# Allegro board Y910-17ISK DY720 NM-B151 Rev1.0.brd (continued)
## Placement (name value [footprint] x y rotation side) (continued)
C659  -  [C_0603NEW]  219.81 130.45 90 bottom
C660  -  [C_0603NEW]  217.46 151.46 0 top
C661  -  [C_0603NEW]  221.65 151.21 180 bottom
C662  -  [C_0402NEW]  222.68 130.76 180 top
C663  -  [C_0402NEW]  226.11 130.51 180 top
C664  -  [C_0402NEW]  226.11 131.4 180 top
C665  -  [C_0603NEW]  217.46 152.73 0 top
C666  VAL  [C_0402-NV]  241.52 131.02 180 top
C667  VAL  [C_0402-NV]  244.22 135.41 0 top
C668  VAL  [C_0402-NV]  244.09 131.04 0 top
C669  VAL  [C_0402-NV]  241.9 133.18 180 top
C670  -  [C_0402NEW]  226.11 132.92 180 top
C671  -  [C_0402NEW]  226.11 133.81 180 top
C672  -  [C_0402NEW]  222.68 134.7 180 top
C673  -  [C_0402NEW]  222.68 135.59 180 top
C674  -  [C_0402NEW]  226.11 135.33 180 top
C675  -  [C_0402NEW]  226.11 136.22 180 top
C676  -  [C_0603NEW]  223.17 128.98 0 bottom
C677  -  [C_0603NEW]  228.38 128.98 180 bottom
C678  -  [C_0603NEW]  216.82 132.41 0 bottom
C679  -  [C_0402NEW]  222.68 137.11 180 top
C680  -  [C_0402NEW]  222.68 138 180 top
C681  -  [C_0402NEW]  226.11 137.75 180 top
C682  -  [C_0402NEW]  226.11 138.64 180 top
C683  -  [C_0603NEW]  212.88 127.08 180 bottom
C684  -  [C_0603NEW]  221.39 125.81 180 top
C685  VAL  [C_0402-NV]  244.04 132.52 270 top
C686  VAL  [C_0402-NV]  249.27 140.8 0 top
C687  -  [C_0603NEW]  223.81 126.95 180 top
C688  VAL  [C_0402-NV]  263.37 132.06 180 top
C689  VAL  [C_0402-NV]  254.78 140.41 270 top
C690  VAL  [C_0402-NV]  259.81 121.62 90 top
C691  VAL  [C_0402-NV]  263.49 123.4 180 top
C692  VAL  [C_0402-NV]  263.24 139.22 180 top
C693  -  [C_0603NEW]  224 123.71 270 top
C694  -  [C_0603NEW]  234.03 124.86 270 top
C695  -  [C_0402NEW]  242.29 120.6 270 top
C696  -  [C_0402NEW]  241.22 120.6 180 top
C697  VAL  [C_0402-NV]  244.19 129.24 0 top
C698  VAL  [C_0402-NV]  260.85 140.41 270 top
C699  -  [C_0402NEW]  44.55 38.1 90 bottom
C701  VAL  [C_0402-NV]  242.16 124.77 0 top
C702  VAL  [C_0402-NV]  241.07 123.14 90 top
C703  VAL  [C_0402-NV]  242.67 122.63 180 top
C704  -  [C_0603NEW]  217.39 127.02 270 bottom
C705  -  [C_0603NEW]  218.66 127.02 270 bottom
C868  -  [C_0402NEW]  222.68 140.41 180 top
C869  -  [C_0402NEW]  222.68 139.53 180 top
C870  -  [C_0402NEW]  226.11 140.16 180 top
C871  -  [C_0402NEW]  183.46 145.29 90 top
C872  -  [C_0402NEW]  184.83 144.22 0 top
C873  -  [C_0402NEW]  184.84 142.19 0 top
C874  -  [C_0402NEW]  226.11 141.05 180 top
C875  -  [C_0402NEW]  222.68 142.7 180 top
C876  -  [C_0402NEW]  222.68 141.81 180 top
C877  -  [C_0402NEW]  226.11 142.57 180 top
C878  -  [C_0402NEW]  226.11 143.46 180 top
C879  -  [C_0402NEW]  222.68 145.24 180 top
C880  -  [C_0402NEW]  222.68 144.35 180 top
C881  -  [C_0402NEW]  226.11 145.11 180 top
C882  -  [C_0402NEW]  226.11 146 180 top
C883  -  [C_0402NEW]  222.68 146.89 180 top
C884  -  [C_0402NEW]  222.68 147.78 180 top
C885  -  [C_0402NEW]  226.11 147.53 180 top
C886  -  [C_0402NEW]  226.11 148.42 180 top
C887  -  [C_0402NEW]  248.98 170.01 0 top
C888  -  [C_0402NEW]  210.66 198.63 90 bottom
C889  -  [C_0402NEW]  245.97 171.2 90 bottom
C890  -  [C_0402NEW]  249.02 171.1 270 bottom
C907  -  [C_0402NEW]  246.97 170.01 180 top
C908  -  [C_0402NEW]  293.01 159.92 0 top
C909  -  [C_0402NEW]  281.15 171.1 270 bottom
C910  -  [C_0402NEW]  294.05 158.83 180 bottom
C915  -  [C_0603NEW]  172.21 138.36 90 top
C916  -  [C_0603NEW]  160.37 133.68 90 top
C917  -  [C_0603NEW]  163.01 133.68 90 top
C918  -  [C_0603NEW]  179.8 133.11 270 top
C919  -  [C_0402NEW]  177.01 134.24 90 top
C920  -  [C_0402NEW]  164.56 133.25 270 top
C921  -  [C_0402NEW]  172.05 133.51 270 top
C922  -  [C_0402NEW]  186.28 134.06 90 top
C923  -  [C_0402NEW]  186.28 133.18 0 top
C924  -  [C_0402NEW]  163.46 138.33 0 top
C925  -  [C_0402NEW]  169.01 138.92 0 top
C926  -  [C_0402NEW]  170.66 133.51 270 top
C927  -  [C_0402NEW]  179.55 134.19 90 top
C928  -  [C_0402NEW]  184.68 136.99 0 top
C929  -  [C_0805NEW]  199.91 169.5 0 top
C930  -  [C_0402NEW]  191.87 157.38 270 top
C931  -  [C_0402NEW]  182.39 155.17 180 top
C932  -  [C_0402NEW]  188.41 156.37 0 top
C933  -  [C_0402NEW]  188.41 157.25 0 top
C934  -  [C_0402NEW]  182.82 152.54 0 top
C935  -  [C_0402NEW]  182.37 151.58 0 top
C936  -  [C_0402NEW]  182.79 149.2 270 top
C937  -  [C_0402NEW]  183.67 149.21 270 top
C938  -  [C_0201NEW]  184.25 157.51 270 top
C939  -  [C_0201NEW]  183.52 155.03 90 top
C940  -  [C_0201NEW]  184.08 155.02 90 top
C941  -  [C_B2]  205.71 169.75 180 bottom
C942  -  [C_B2]  202.87 169.75 0 bottom
C944  -  [C_0201NEW]  184.67 150.83 0 top
C945  -  [C_0201NEW]  186.32 152.73 180 top
C946  -  [C_0201NEW]  185.14 149.65 90 top
C947  -  [C_0201NEW]  184.63 151.95 0 top
C948  -  [C_0201NEW]  184.63 151.39 0 top
C949  -  [C_0402NEW]  177.03 138.33 90 top
C950  -  [C_0201NEW]  154.27 139.06 270 top
C951  -  [C_0201NEW]  186.38 138.57 270 top
C952  -  [C_B2]  173.22 171.4 180 bottom
C953  -  [C_B2]  194.94 168.74 180 top
C954  -  [C_B2]  195.06 169.75 180 bottom
C955  -  [C_0603NEW]  160.43 173.43 0 top
C956  -  [C_0603NEW]  160.43 174.7 0 top
C957  -  [C_0603NEW]  160.94 169.37 0 bottom
C958  -  [C_0603NEW]  160.89 170.69 0 bottom
C959  -  [C_0603NEW]  160.81 172.04 0 bottom
C960  -  [C_0603NEW]  154.21 174.83 180 top
C961  -  [C_0603NEW]  154.21 173.56 180 top
C962  -  [C_0603NEW]  165.51 172.55 180 bottom
C974  -  [C_0402NEW]  172.07 150.09 270 top
C975  -  [C_0402NEW]  177.4 149.18 90 top
C976  -  [C_0402NEW]  176.51 149.18 90 top
C977  -  [C_0402NEW]  175.62 150.09 270 top
C978  -  [C_0402NEW]  174.73 150.09 270 top
C979  -  [C_0402NEW]  176.37 146.76 180 top
C980  -  [C_0402NEW]  179.71 152.57 270 top
C981  -  [C_0402NEW]  178.28 152.61 270 top
C982  -  [C_0402NEW]  176.4 152.57 270 top
C983  -  [C_0402NEW]  172.57 143.78 0 top
C984  -  [C_0402NEW]  173.61 152.55 270 top
C985  -  [C_0402NEW]  172.09 151.63 90 top
C986  -  [C_0402NEW]  182.27 143.11 0 top
C987  -  [C_0402NEW]  173.15 147.81 180 top
C988  -  [C_0402NEW]  180.14 149.18 90 top
C1007  -  [C_0402NEW]  172.95 149.18 90 top
C1008  -  [C_0402NEW]  173.84 149.18 90 top
C1009  -  [C_0402NEW]  179.23 150.09 270 top
C1010  -  [C_0402NEW]  182.26 140.35 0 top
C1011  -  [C_0402NEW]  182.26 144 0 top
C1012  -  [C_0402NEW]  181.17 139.59 180 top
C1013  -  [C_0402NEW]  181.84 138.29 180 top
C1014  -  [C_0402NEW]  175.49 143.78 180 top
C1015  -  [C_0402NEW]  176.43 143.78 0 top
C1016  -  [C_0402NEW]  179.17 143.78 180 top
C1017  -  [C_0402NEW]  180.29 143.81 0 top
C1018  -  [C_0402NEW]  182.21 141.68 0 top
C1019  -  [C_0402NEW]  177.97 138.28 0 top
C1020  -  [C_0402NEW]  174.63 138.32 180 top
C1021  -  [C_0402NEW]  178.34 150.09 270 top
C1040  -  [C_0201NEW]  179.35 156.62 270 top
C1041  -  [C_0201NEW]  178.8 156.62 270 top
C1042  -  [C_0201NEW]  175.42 154.02 270 top
C1043  -  [C_0201NEW]  174.86 154.02 270 top
C1044  -  [C_0201NEW]  173.12 139.53 0 top
C1045  -  [C_0201NEW]  180.37 156.62 270 top
C1046  -  [C_0201NEW]  180.93 156.62 270 top
C1047  -  [C_0201NEW]  176.43 156.62 270 top
C1048  -  [C_0201NEW]  176.99 156.62 270 top
C1049  -  [C_0201NEW]  174.63 156.62 270 top
C1050  -  [C_0201NEW]  174.07 156.62 270 top
C1051  -  [C_0201NEW]  175.42 152.06 270 top
C1052  -  [C_0201NEW]  174.86 152.06 270 top
C1053  -  [C_0201NEW]  179.35 154 270 top
C1054  -  [C_0201NEW]  175.86 148.03 0 top
C1055  -  [C_0201NEW]  175.86 147.48 0 top
C1056  -  [C_0201NEW]  172.57 146.51 0 top
C1057  -  [C_0201NEW]  176.08 139.47 180 top
C1058  -  [C_0201NEW]  174.76 146.89 180 top
C1059  -  [C_0201NEW]  178.32 146.89 180 top
C1060  -  [C_0201NEW]  181.16 146.26 0 top
C1061  -  [C_0201NEW]  179.38 146.89 0 top
C1062  -  [C_0201NEW]  177.39 151.46 90 top
C1086  -  [C_0201NEW]  179.42 148.03 0 top
C1087  -  [C_0201NEW]  179.42 147.48 0 top
C1088  -  [C_0201NEW]  178.28 148.03 180 top
C1089  -  [C_0201NEW]  178.28 147.48 180 top
C1090  -  [C_0201NEW]  178.99 140.03 180 top
C1091  -  [C_0201NEW]  178.99 139.47 180 top
C1092  -  [C_0201NEW]  174.29 140.03 0 top
C1093  -  [C_0201NEW]  174.29 139.47 0 top
C1094  -  [C_0201NEW]  180.21 141.18 0 top
C1095  -  [C_0201NEW]  180.21 140.62 0 top
C1096  -  [C_0201NEW]  179.04 141.43 180 top
C1097  -  [C_0201NEW]  179.04 140.87 180 top
C1098  -  [C_0201NEW]  176.5 141.43 0 top
C1099  -  [C_0201NEW]  176.5 140.87 0 top
C1100  -  [C_0201NEW]  180.94 148.03 0 top
C1101  -  [C_0201NEW]  180.94 147.48 0 top
C1102  -  [C_0201NEW]  175.43 141.43 180 top
C1103  -  [C_0201NEW]  175.43 140.87 180 top
C1104  -  [C_0201NEW]  181.45 149.61 270 top
C1105  -  [C_0201NEW]  182.01 149.61 270 top
C1106  -  [C_0201NEW]  173.06 154.02 270 top
C1107  -  [C_0201NEW]  172.5 154.02 270 top
C1108  -  [C_0201NEW]  181.16 154.02 270 top
C1132  -  [C_0201NEW]  172.44 141.43 0 top
C1133  -  [C_0201NEW]  172.44 140.87 0 top
C1134  -  [C_0201NEW]  174.72 148.03 180 top
C1135  -  [C_0201NEW]  174.72 147.48 180 top
C1136  -  [C_0201NEW]  180.82 142.57 0 top
C1137  -  [C_0201NEW]  180.82 142.01 0 top
C1138  -  [C_0201NEW]  180 142.57 180 top
C1139  -  [C_0201NEW]  180 142.01 180 top
C1140  -  [C_0201NEW]  178.25 142.57 0 top
C1141  -  [C_0201NEW]  178.25 142.01 0 top
C1142  -  [C_0201NEW]  177.21 142.57 180 top
C1143  -  [C_0201NEW]  177.21 142.01 180 top
C1144  -  [C_0201NEW]  174.59 142.65 0 top
C1145  -  [C_0201NEW]  174.59 142.09 0 top
C1146  -  [C_0201NEW]  177.78 154.02 270 top
C1147  -  [C_0201NEW]  173.54 142.66 180 top
C1148  -  [C_0201NEW]  180.56 152.05 270 top
C1149  -  [C_0201NEW]  181.72 154 270 top
C1150  -  [C_0201NEW]  173.54 142.1 180 top
C1151  -  [C_0201NEW]  172.82 152.04 270 top
C1152  -  [C_0201NEW]  178.8 154.02 270 top
C1153  -  [C_0201NEW]  181.2 152.06 270 top
C1154  -  [C_0201NEW]  177.22 154.02 270 top
C1178  -  [C_B2]  155.95 169.75 0 bottom
C1179  -  [C_B2]  156.03 169.37 0 top
C1180  -  [C_B2]  185.67 171.66 180 bottom
C1181  -  [C_0805NEW]  187.64 174.7 180 bottom
C1182  -  [C_0805NEW]  175.14 174.2 0 bottom
C1183  -  [C_0805NEW]  187.38 168.99 180 bottom
C1184  -  [C_0805NEW]  163.08 174.07 0 bottom
C1326  -  [C_0402NEW]  282.4 170.38 180 top
C1327  -  [C_0805NEW]  178.66 194.35 270 bottom
C1329  -  [C_0402NEW]  300.58 58.3 90 top
C1330  -  [C_0402NEW]  303.68 58.25 0 top
C1332  -  [C_0402NEW]  300.53 61.29 180 top
C1333  -  [C_0402NEW]  303.7 69.42 180 top
C1335  -  [C_B2]  16.76 65.23 180 top
C1338  -  [C_0402NEW]  295.07 72.98 180 top
C1339  -  [C_0402NEW]  303.58 73.23 180 top
C1340  -  [C_0402NEW]  205.61 130.64 180 bottom
C1341  -  [C_0402NEW]  210.79 154.71 90 top
C1342  -  [C_0402NEW]  292.91 173.31 180 top
C1343  VAL  [C_0402-NV]  242.29 126.83 0 top
C1353  -  [C_0402NEW]  293.14 124.84 0 top
C1354  -  [C_0402NEW]  294.22 126.8 180 bottom
C1355  -  [C_0402NEW]  294.18 123.78 180 bottom
C1359  -  [C_0402NEW]  64.66 9.22 0 top
C1361  -  [C_0402NEW]  64.66 8.33 0 top
C1362  -  [C_0402NEW]  75.15 15.9 270 top
C1363  -  [C_0402NEW]  77.69 6.61 90 top
C1364  -  [C_0402NEW]  65.76 3.81 90 top
C1365  -  [C_0402NEW]  66.64 3.81 90 top
C1367  -  [C_0402NEW]  66.34 7.32 180 top
C1368  -  [C_0402NEW]  75.03 5.36 270 top
C1369  -  [C_0402NEW]  76.8 4.45 90 top
C1370  -  [C_0402NEW]  57.37 12.22 270 bottom
C1371  -  [C_B2]  62.71 16.99 270 bottom
C1372  -  [C_0402NEW]  65.37 17.66 90 bottom
C1373  -  [C_0402NEW]  257.86 92.61 270 top
C1374  -  [C_0402NEW]  259.94 91.57 90 bottom
C1375  -  [C_0402NEW]  257.91 91.52 90 bottom
C1376  -  [C_0402NEW]  91 17.73 0 top
C1377  -  [C_0402NEW]  89.25 18.57 270 top
C1378  -  [C_0402NEW]  90.14 18.57 270 top
C1379  -  [C_0603NEW]  88.11 17.42 90 top
C1385  -  [C_0402NEW]  288.94 22 0 top
C1386  -  [C_0603NEW]  288.7 20.91 0 top
C1391  -  [C_0402NEW]  307.61 105.49 0 top
C1392  -  [C_0603NEW]  307.37 104.4 0 top
C1393  -  [C_0603NEW]  219.93 127.02 270 bottom
C1394  VAL  [C_0402-NV]  230.35 124.54 90 bottom
C1395  VAL  [C_0402-NV]  226.03 127.84 0 bottom
C1396  VAL  [C_0402-NV]  218.41 126.7 270 top
C1397  VAL  [C_0402-NV]  244.19 124.67 0 top
C1398  VAL  [C_0402-NV]  221.08 126.32 270 bottom
C1399  -  [C_0402NEW]  222.6 114.33 270 bottom
C1400  -  [C_0402NEW]  222.6 115.19 90 bottom
C1401  -  [C_0402NEW]  281.78 86.87 90 bottom
C1402  -  [C_0402NEW]  280.77 86.87 90 bottom
C1405  VAL  [C_0402-NV]  244.19 127.51 0 top
C1406  VAL  [C_0402-NV]  244.19 128.35 0 top
C1407  VAL  [C_0402-NV]  225.9 123.9 180 bottom
C2027  -  [C_0201NEW]  58.57 75.76 270 bottom
C2028  -  [C_0201NEW]  56.94 77.64 90 bottom
C2029  -  [C_0201NEW]  59.2 75.76 270 bottom
C2030  -  [C_0201NEW]  57.58 77.64 90 bottom
C2031  -  [C_0201NEW]  54.55 78.25 270 bottom
C2032  -  [C_0201NEW]  55.72 73.57 90 bottom
C2033  -  [C_0201NEW]  55.19 78.25 270 bottom
C2034  -  [C_0201NEW]  56.36 73.57 90 bottom
C2035  -  [C_0201NEW]  52.17 76.44 270 bottom
C2036  -  [C_0201NEW]  48.06 74.37 0 bottom
C2037  -  [C_0201NEW]  52.8 76.44 270 bottom
C2038  -  [C_0201NEW]  48.06 73.74 0 bottom
C2039  -  [C_0201NEW]  49.4 77.36 270 bottom
C2040  -  [C_0201NEW]  47.47 77.77 90 bottom
C2041  -  [C_0201NEW]  50.03 77.36 270 bottom
C2042  -  [C_0201NEW]  48.1 77.77 90 bottom
C2043  -  [C_0201NEW]  69.78 74.37 0 bottom
C2044  -  [C_0201NEW]  69.78 73.82 0 bottom
C2045  -  [C_0201NEW]  69.78 72.85 0 bottom
C2046  -  [C_0402NEW]  44.37 78.57 180 bottom
C2047  -  [C_0201NEW]  69.78 72.29 0 bottom
C2048  -  [C_0402NEW]  45.23 78.57 0 bottom
C2049  -  [C_0201NEW]  69.78 71.33 0 bottom
C2050  -  [C_0201NEW]  69.78 70.77 0 bottom
C2051  -  [C_0201NEW]  69.78 69.85 0 bottom
C2052  -  [C_0201NEW]  69.78 69.29 0 bottom
C2055  -  [C_0201NEW]  53.82 99.05 270 top
C2056  -  [C_0201NEW]  59.82 63.58 0 bottom
C2057  -  [C_0201NEW]  59.82 63.02 0 bottom
C2058  -  [C_0201NEW]  59.82 62.34 0 bottom
C2059  -  [C_0201NEW]  59.82 61.78 0 bottom
C2060  -  [C_0201NEW]  59.82 61.14 0 bottom
C2061  -  [C_0201NEW]  59.82 60.58 0 bottom
C2062  -  [C_0201NEW]  59.82 59.85 0 bottom
C2063  -  [C_0201NEW]  59.82 59.26 0 bottom
C2066  -  [C_0201NEW]  44.1 83.98 180 bottom
C2067  -  [C_0201NEW]  44.1 83.42 180 bottom
C2068  -  [C_0201NEW]  44.1 82.25 180 bottom
C2069  -  [C_0201NEW]  44.1 82.81 180 bottom
C2070  -  [C_0201NEW]  30.12 68.82 90 bottom
C2071  -  [C_0201NEW]  29.56 68.82 90 bottom
C2072  -  [C_0201NEW]  52.01 83.23 270 top
C2073  -  [C_0201NEW]  52.41 83.85 0 top
C2074  -  [C_0201NEW]  49.44 86.52 180 top
C2076  -  [C_0201NEW]  51.09 88.42 0 top
C2077  -  [C_0201NEW]  52.52 85.79 270 top
C2078  -  [C_0201NEW]  53.18 85.71 315 top
C2079  -  [C_0201NEW]  53.08 88.24 45 top
C2080  -  [C_0201NEW]  53.35 87.58 0 top
C2081  -  [C_0201NEW]  52.52 88.87 90 top
C2082  -  [C_0201NEW]  47.78 88.95 180 top
C2083  -  [C_0201NEW]  42.39 90.82 90 top
C2084  -  [C_0201NEW]  48.14 87.84 180 top
C2085  -  [C_0402NEW]  42.26 90.68 90 bottom
C2086  -  [C_0402NEW]  41.37 90.68 90 bottom
C2087  -  [C_0402NEW]  43.15 90.68 90 bottom
C2088  -  [C_0402NEW]  44.04 90.68 90 bottom
C2089  -  [C_0201NEW]  51.09 87.84 0 top
C2090  -  [C_0201NEW]  50.05 86.9 315 top
C2091  -  [C_0201NEW]  48.79 88.16 135 top
C2092  -  [C_0201NEW]  47.54 86.15 90 top
C2093  -  [C_0201NEW]  46.92 85.88 180 top
C2094  -  [C_0201NEW]  46.22 85.28 270 top
C2095  -  [C_0201NEW]  47.41 84.94 315 top
C2096  -  [C_0201NEW]  49.97 80.09 0 top
C2097  -  [C_0201NEW]  50.57 84.93 90 top
C2098  -  [C_0201NEW]  49.97 80.72 0 top
C2099  -  [C_0201NEW]  49.97 81.36 0 top
C2100  -  [C_0402NEW]  54.58 98.83 270 top
C2101  -  [C_0201NEW]  52.34 87.25 180 top
C2102  -  [C_0201NEW]  51.46 86.62 225 top
C2103  -  [C_0603NEW]  42.01 94.38 270 bottom
C2104  -  [C_0603NEW]  43.28 94.38 270 bottom
C2105  -  [C_0603NEW]  40.74 94.38 270 bottom
C2107  -  [C_0201NEW]  49.4 83.81 270 top
C2108  -  [C_0201NEW]  49.44 84.61 180 top
C2109  -  [C_0402NEW]  45.94 83.47 270 top
C2110  -  [C_0402NEW]  46.12 87.51 270 top
C2111  -  [C_0201NEW]  48.25 87.14 270 top
C2112  -  [C_0201NEW]  48.66 83.25 90 top
C2113  -  [C_0603NEW]  38.32 79.01 270 bottom
C2114  -  [C_0603NEW]  35.78 80.03 90 top
C2115  -  [C_0603NEW]  37.05 80.03 90 top
C2116  -  [C_0603NEW]  36.8 80.03 90 bottom
C2117  -  [C_0201NEW]  32.1 69.08 270 bottom
C2118  -  [C_0201NEW]  36.96 72.34 180 top
C2119  -  [C_0603NEW]  38.32 75.33 270 bottom
C2120  -  [C_B2]  40.63 77.04 180 top
C2121  -  [C_0201NEW]  28.54 69.21 270 bottom
C2122  -  [C_0402NEW]  13.74 80.52 90 bottom
C2123  -  [C_0402NEW]  13.56 77.63 270 bottom
C2124  -  [C_0402NEW]  36.29 70.13 270 bottom
C2125  -  [C_0402NEW]  14.62 80.52 90 bottom
C2126  -  [C_0402NEW]  14.45 76.71 90 bottom
C2127  -  [C_0201NEW]  33.48 71.02 0 top
C2128  -  [C_0201NEW]  31.72 73.45 90 top
C2129  -  [C_0201NEW]  30.41 77.3 0 top
C2130  -  [C_0201NEW]  30.41 76.66 0 top
C2131  -  [C_0201NEW]  32.74 74.84 90 top
C2133  -  [C_0402NEW]  60.24 86.06 180 top
C2134  -  [C_0402NEW]  60.24 85.17 180 top
C2136  -  [C_0603NEW]  30.17 80.59 90 bottom
C2139  -  [C_0402NEW]  29.43 79.76 90 top
C2151  -  [C_0201NEW]  51.89 85.16 270 top
C2153  -  [C_0402NEW]  58.85 87.07 180 top
C2154  -  [C_0402NEW]  58.85 87.96 180 top
C2163  -  [C_0201NEW]  84.77 84.79 0 bottom
C2164  -  [C_0201NEW]  84.77 83.26 0 bottom
C2165  -  [C_0201NEW]  84.77 87.84 0 bottom
C2166  -  [C_0402NEW]  82.82 86.08 0 top
C2167  -  [C_0402NEW]  82.8 82.99 0 top
C2168  -  [C_0402NEW]  82.82 87.46 0 top
C2169  -  [C_0402NEW]  79.78 82.76 0 top
C2170  -  [C_0402NEW]  80.94 88.85 180 top
C2171  -  [C_0402NEW]  85.64 78.06 180 top
C2172  -  [C_0603NEW]  84.74 79.2 0 top
C2174  -  [C_0805NEW]  220.06 107.94 90 bottom
C2175  -  [C_B2]  222.6 108.23 270 bottom
C2176  -  [C_0603NEW]  282.5 128.73 0 top
C2177  -  [C_0603NEW]  274.43 157.47 90 top
C2178  -  [C_0603NEW]  273.16 157.47 90 top
C2179  -  [C_0603NEW]  282.5 123.78 0 top
C2180  -  [C_0603NEW]  257.02 157.37 90 top
C2181  -  [C_0603NEW]  255.75 157.37 90 top
C2182  -  [C_0603NEW]  238.16 158.96 180 top
C2183  -  [C_0603NEW]  282.35 133.94 0 top
C2184  -  [C_0603NEW]  282.35 132.67 0 top
C2185  -  [C_0603NEW]  282.73 116.41 0 top
C2186  -  [C_0603NEW]  282.73 117.68 0 top
C2187  -  [C_0603NEW]  263.11 107.59 270 top
C2188  -  [C_0603NEW]  261.08 107.59 270 top
C2189  VAL  [C_0402-NV]  245.33 118.7 270 top
C2193  VAL  [C_0402-NV]  246.25 121.49 90 top
C2198  VAL  [C_0402-NV]  248.53 121.49 90 top
C2204  VAL  [C_0402-NV]  223.62 122.25 0 bottom
C2207  VAL  [C_0402-NV]  245.41 121.49 90 top
C2208  VAL  [C_0402-NV]  250.21 121.49 90 top
C2209  VAL  [C_0402-NV]  249.52 119.33 270 top
C2210  VAL  [C_0402-NV]  243.71 119.84 0 top
C2211  VAL  [C_0402-NV]  244.27 121.19 0 top
C2212  VAL  [C_0402-NV]  244.27 122.03 0 top
C2213  VAL  [C_0402-NV]  244.06 118.57 0 top
C2214  VAL  [C_0402-NV]  247.11 117.81 180 top
C2215  VAL  [C_0402-NV]  247.42 121.11 180 top
C2216  VAL  [C_0402-NV]  247.49 119.21 270 top
C2217  VAL  [C_0402-NV]  233.78 112.35 270 bottom
C2218  VAL  [C_0402-NV]  247.11 116.92 180 top
C2219  VAL  [C_0402-NV]  249.37 121.49 90 top
C2220  VAL  [C_0402-NV]  232.89 112.35 270 bottom
C2221  -  [C_0402NEW]  286.56 174.2 180 top
C2222  -  [C_0402NEW]  300.78 77.68 180 top
C2319  VAL  [C_0402-NV]  252.19 121.11 0 top
C2320  -  [C_0603NEW]  250.92 104.28 270 top
C2321  VAL  [C_0402-NV]  262.1 140.16 0 top
C2322  -  [C_0603NEW]  248.64 104.28 270 top
C2323  -  [C_0603NEW]  242.29 141.24 270 top
C2324  VAL  [C_0402-NV]  260.06 133.81 0 top
C2325  VAL  [C_0402-NV]  261.58 133.81 0 top
C2326  VAL  [C_0402-NV]  247.37 125.43 180 top
C2327  -  [C_0603NEW_S]  250.89 135.22 270 top
C2328  VAL  [C_0402-NV]  252.02 125.43 0 top
C2329  VAL  [C_0402-NV]  253.33 121.49 90 top
C2330  VAL  [C_0402-NV]  250.47 125.43 0 top
C2331  VAL  [C_0402-NV]  248.92 125.43 0 top
C2332  VAL  [C_0402-NV]  257.78 140.92 0 top
C2333  -  [C_0603NEW]  241.27 147.08 90 top
C2334  VAL  [C_0402-NV]  245.82 125.43 180 top
C2335  -  [C_0603NEW_S]  248.79 135.22 270 top
C2336  VAL  [C_0402-NV]  263.49 127.21 270 top
C2337  VAL  [C_0402-NV]  260.45 124.03 0 top
C2338  VAL  [C_0402-NV]  257.41 124.03 0 top
C2339  VAL  [C_0402-NV]  252.27 140.41 270 top
C2340  VAL  [C_0402-NV]  253.97 124.03 180 top
C2341  VAL  [C_0402-NV]  252.45 138 180 top
C2342  -  [C_0603NEW]  239.17 143.21 180 top
C2343  VAL  [C_0402-NV]  249.27 140.03 0 top
C2344  VAL  [C_0402-NV]  257.78 122 0 top
C2345  -  [C_0603NEW_S]  256.59 126.82 270 top
C2346  VAL  [C_0402-NV]  254.6 122 0 top
C2347  VAL  [C_0402-NV]  263.49 125.94 180 top
C2348  VAL  [C_0402-NV]  252.02 128.22 0 top
C2349  VAL  [C_0402-NV]  262.03 124.03 0 top
C2350  VAL  [C_0402-NV]  250.47 128.22 0 top
C2351  VAL  [C_0402-NV]  263.49 122.51 180 top
C2352  -  [C_0603NEW]  239.43 149.69 0 top
C2353  VAL  [C_0402-NV]  248.92 128.22 0 top
C2354  -  [C_0603NEW]  260.83 130.32 90 top
C2355  VAL  [C_0402-NV]  247.37 128.22 180 top
C2356  VAL  [C_0402-NV]  252.19 121.95 0 top
C2357  VAL  [C_0402-NV]  256.26 140.92 0 top
C2358  VAL  [C_0402-NV]  252.02 126.83 0 top
C2359  VAL  [C_0402-NV]  250.47 126.83 0 top
C2360  VAL  [C_0402-NV]  248.92 126.83 0 top
C2361  VAL  [C_0402-NV]  255.76 124.03 180 top
C2362  VAL  [C_0402-NV]  253.11 140.41 270 top
C2363  -  [C_0603NEW_S]  257.99 126.82 270 top
C2364  VAL  [C_0402-NV]  247.37 126.83 180 top
C2365  VAL  [C_0402-NV]  245.82 126.83 180 top
C2366  VAL  [C_0402-NV]  261.97 122 0 top
C2367  VAL  [C_0402-NV]  245.82 128.22 180 top
C2368  VAL  [C_0402-NV]  263.24 138.38 180 top
C2369  VAL  [C_0402-NV]  260.07 138 0 top
C2370  VAL  [C_0402-NV]  256.9 138 180 top
C2371  -  [C_0603NEW]  259.56 131.72 270 top
C2372  VAL  [C_0402-NV]  247.42 122 180 top
C2373  VAL  [C_0402-NV]  261.6 138 0 top
C2374  VAL  [C_0402-NV]  255.48 136.6 180 top
C2375  -  [C_0603NEW]  257.02 130.32 90 top
C2376  VAL  [C_0402-NV]  257.01 136.6 180 top
C2377  VAL  [C_0402-NV]  258.53 136.6 0 top
C2378  VAL  [C_0402-NV]  260.06 136.6 0 top
C2379  VAL  [C_0402-NV]  258.55 138 0 top
C2380  -  [C_0603NEW]  254.48 130.32 90 top
C2381  VAL  [C_0402-NV]  250.74 124.03 0 top
C2382  VAL  [C_0402-NV]  247.45 124.03 0 top
C2383  -  [C_0603NEW]  250.67 131.72 270 top
C2384  VAL  [C_0402-NV]  251.05 140.03 180 top
C2385  VAL  [C_0402-NV]  263.11 135.13 180 top
C2386  VAL  [C_0402-NV_S]  249.02 136.6 0 top
C2387  VAL  [C_0402-NV_S]  250.67 136.6 0 top
C2388  -  [C_0603NEW]  249.4 130.32 90 top
C2389  VAL  [C_0402-NV]  258.93 124.03 0 top
C2390  -  [C_0603NEW]  248.13 131.72 270 top
C2391  VAL  [C_0402-NV]  250.67 138 0 top
C2392  VAL  [C_0402-NV]  263.11 133.94 180 top
C2393  VAL  [C_0402-NV]  257.78 140.08 0 top
C2394  -  [C_0603NEW]  265.41 119.7 315 top
C2395  -  [C_0603NEW]  264.32 137.24 180 top
C2396  -  [C_0603NEW]  264.32 129.11 180 top
C2397  -  [C_0603NEW]  272.12 139.79 135 top
C2398  VAL  [C_0402-NV]  251.05 121.49 90 top
C2399  VAL  [C_0402-NV]  259.18 140.41 270 top
C2400  VAL  [C_0402-NV]  255.8 121.62 90 top
C2401  VAL  [C_0402-NV]  257.78 121.11 0 top
C2402  VAL  [C_0402-NV]  258.92 121.62 90 top
C2403  VAL  [C_0402-NV]  260.7 121.62 90 top
C2404  VAL  [C_0402-NV]  261.97 121.11 0 top
C2405  VAL  [C_0402-NV]  263.49 131.14 180 top
C2406  VAL  [C_0402-NV]  263.49 124.79 180 top
C2407  VAL  [C_0402-NV]  256.64 121.62 90 top
C2408  -  [C_0603NEW]  263.51 140.81 45 top
C2409  -  [C_0603NEW]  264.5 120.24 135 top
C2410  -  [C_0201NEW]  84.77 82.63 0 bottom
C2411  -  [C_0201NEW]  84.77 87.2 0 bottom
C2412  -  [C_0201NEW]  84.77 85.68 0 bottom
C2413  -  [C_0201NEW]  84.77 86.31 0 bottom
C2414  -  [C_0201NEW]  84.77 84.15 0 bottom
C2415  VAL  [C_0402-NV]  254.6 121.11 0 top
C2416  VAL  [C_0402-NV]  241.14 129.87 90 top
C2425  -  [C_0402NEW]  293.14 125.76 0 top
C2439  -  [C_0402NEW]  258.85 92.61 270 top
C2440  -  [C_B2]  216.1 177.88 0 top
C2441  -  [C_B2]  273.17 184.74 180 top
C2442  VAL  [C_0402-NV]  244.19 126.57 0 top
C2443  VAL  [C_0402-NV]  228.7 124.54 90 bottom
C2444  VAL  [C_0402-NV]  223.11 127.84 180 bottom
C2445  VAL  [C_0402-NV]  244.19 125.73 0 top
C2446  VAL  [C_0402-NV]  244.19 123.78 0 top
C2447  VAL  [C_0402-NV]  244.32 122.89 0 top
C2448  -  [C_0603NEW]  230.45 173.34 90 top
C2449  -  [C_0603NEW]  230.45 176.08 90 top
C2450  -  [C_0603NEW]  246.45 176.54 90 top
C2451  -  [C_0603NEW]  246.1 178.58 270 bottom
C2452  -  [C_0603NEW]  238.67 179.78 0 bottom
C2453  -  [C_0603NEW]  231.59 168.56 90 top
C2454  -  [C_0603NEW]  231.72 173.34 90 top
C2455  -  [C_0603NEW]  231.72 176.08 90 top
C2456  -  [C_0603NEW]  245.18 176.54 90 top
C2457  -  [C_0603NEW]  231.11 177.18 90 bottom
C2458  -  [C_0603NEW]  241.08 179.78 0 bottom
C2459  -  [C_0402NEW]  245.08 173.96 90 top
C2460  -  [C_0402NEW]  240 168.17 90 top
C2461  -  [C_0402NEW]  245.23 167.08 270 top
C2462  -  [C_0402NEW]  245.23 165.25 270 top
C2463  -  [C_0402NEW]  230.98 173.36 90 bottom
C2464  -  [C_0402NEW]  230.98 175.14 90 bottom
C2465  -  [C_0402NEW]  240.83 171.59 270 top
C2466  -  [C_0402NEW]  245.97 165.26 270 bottom
C2467  -  [C_0402NEW]  236.96 168.39 90 top
C2468  -  [C_0402NEW]  239.18 173.97 270 top
C2469  -  [C_0402NEW]  237.72 176.37 90 top
C2470  -  [C_0402NEW]  236.07 171.47 90 top
C2471  -  [C_0402NEW]  237 166.79 180 top
C2472  -  [C_0402NEW]  245.93 167.16 270 bottom
C2473  -  [C_0402NEW]  245.97 173.87 90 bottom
C2474  -  [C_0402NEW]  231.94 166.81 270 top
C2475  -  [C_0402NEW]  240 165.88 90 top
C2476  -  [C_0402NEW]  229.97 173.36 90 bottom
C2477  -  [C_0603NEW]  264.45 167.47 180 top
C2478  -  [C_0603NEW]  264.36 168.97 90 top
C2479  -  [C_0603NEW]  248.48 176.41 90 top
C2480  -  [C_0603NEW]  264.13 176.42 90 bottom
C2481  -  [C_0603NEW]  249.14 176.29 90 bottom
C2482  -  [C_0603NEW]  263.26 176.41 90 top
C2483  -  [C_0603NEW]  263.26 164.55 90 top
C2484  -  [C_0603NEW]  249.8 176.43 90 top
C2485  -  [C_0603NEW]  249.8 173.84 90 top
C2486  -  [C_0603NEW]  257.33 179.78 0 bottom
C2487  -  [C_0603NEW]  256.32 179.78 180 bottom
C2488  -  [C_0402NEW]  263.19 175.42 270 top
C2489  -  [C_0402NEW]  263.12 169.21 90 top
C2490  -  [C_0402NEW]  255.82 174.3 270 top
C2491  -  [C_0402NEW]  258.93 171.47 90 top
C2492  -  [C_0402NEW]  258.04 168.34 90 top
C2493  -  [C_0402NEW]  249.02 165.01 270 bottom
C2494  -  [C_0402NEW]  249.02 173.99 90 bottom
C2495  -  [C_0402NEW]  249.98 165.03 270 top
C2496  -  [C_0402NEW]  254.93 168.42 90 top
C2497  -  [C_0402NEW]  254.04 171.53 270 top
C2498  -  [C_0402NEW]  257.28 176.27 90 top
C2499  -  [C_0402NEW]  258.11 165.97 270 top
C2500  -  [C_0402NEW]  249.02 166.81 270 bottom
C2501  -  [C_0402NEW]  263.98 175.42 270 bottom
C2502  -  [C_0402NEW]  248.89 173.13 270 bottom
C2503  -  [C_0402NEW]  264 173.51 270 bottom
C2504  -  [C_0402NEW]  249.98 166.86 270 top
C2505  -  [C_0402NEW]  254.93 165.92 270 top
C2506  -  [C_0402NEW]  266.03 175.39 90 bottom
C2507  -  [C_0402NEW]  266.03 173.49 90 bottom
C2508  -  [C_0402NEW]  281.02 167.41 270 bottom
C2509  -  [C_0402NEW]  281.02 165.38 270 bottom
C2510  -  [C_0402NEW]  275.13 165.83 90 top
C2511  -  [C_0402NEW]  280.2 167.33 270 top
C2512  -  [C_0402NEW]  275.12 169.44 270 top
C2513  -  [C_0402NEW]  272.78 176.33 90 top
C2514  -  [C_0603NEW]  279.02 179 180 top
C2515  -  [C_0603NEW]  279.02 180.4 180 top
C2516  -  [C_0603NEW]  266.82 164.83 90 top
C2517  -  [C_0603NEW]  266.8 176.55 90 top
C2518  -  [C_0603NEW]  281.15 178.96 270 bottom
C2519  -  [C_0603NEW]  280.44 176.98 270 top
C2520  -  [C_0603NEW]  265.09 176.42 90 top
C2521  -  [C_0603NEW]  266.69 173.21 90 top
C2522  -  [C_0603NEW]  272.45 179.78 0 bottom
C2523  -  [C_0603NEW]  265.91 177.82 90 bottom
C2524  -  [C_0603NEW]  270.16 179.78 180 bottom
C2525  -  [C_0402NEW]  280.2 165.4 270 top
C2526  -  [C_0402NEW]  271.89 165.98 270 top
C2527  -  [C_0402NEW]  281.02 173.99 90 bottom
C2528  -  [C_0402NEW]  281.02 173.13 270 bottom
C2529  -  [C_0402NEW]  275.88 171.55 270 top
C2530  -  [C_0402NEW]  274.36 174.04 270 top
C2531  -  [C_0402NEW]  271.12 171.48 90 top
C2532  -  [C_0402NEW]  271.89 168.36 90 top
C2533  -  [C_0402NEW]  280.2 173.88 270 top
C2534  -  [C_0402NEW]  266.8 168.5 270 top
C2535  -  [C_0603NEW]  302.86 146.57 90 bottom
C2536  -  [C_0603NEW]  301.99 146.57 90 top
C2537  -  [C_0603NEW]  300.24 144.62 0 top
C2538  -  [C_0603NEW]  297.62 144.62 0 top
C2539  -  [C_0603NEW]  302.86 150.38 90 bottom
C2540  -  [C_0603NEW]  302.09 156.33 270 top
C2541  -  [C_0603NEW]  301.96 150.47 90 top
C2542  -  [C_0603NEW]  299 158.08 0 top
C2543  -  [C_0603NEW]  300.51 143.72 0 bottom
C2544  -  [C_0603NEW]  302.86 156.35 270 bottom
C2545  -  [C_0603NEW]  288.15 144.36 0 top
C2546  -  [C_0402NEW]  298.47 143.84 0 bottom
C2547  -  [C_0402NEW]  299.2 150.47 0 top
C2548  -  [C_0402NEW]  295.94 158.86 180 bottom
C2549  -  [C_0402NEW]  297.71 158.83 0 bottom
C2550  -  [C_0402NEW]  288.95 149.79 180 top
C2551  -  [C_0402NEW]  288.09 158.04 180 top
C2552  -  [C_0402NEW]  293.16 157.97 0 top
C2553  -  [C_0402NEW]  296.88 157.97 180 top
C2554  -  [C_0402NEW]  287.83 158.83 180 bottom
C2555  -  [C_0402NEW]  296.72 143.84 180 bottom
C2556  -  [C_0402NEW]  297.16 151.95 180 top
C2557  -  [C_0402NEW]  294.45 148.95 0 top
C2558  -  [C_0402NEW]  289.92 158.04 180 top
C2559  -  [C_0402NEW]  288.93 152.96 180 top
C2560  -  [C_0402NEW]  291.17 149.71 0 top
C2561  -  [C_0402NEW]  292.28 152.96 180 top
C2562  -  [C_0402NEW]  291.77 144.45 180 top
C2563  -  [C_0402NEW]  289.73 158.83 180 bottom
C2564  -  [C_0402NEW]  294.53 136.63 0 top
C2565  -  [C_0402NEW]  288.27 126.85 180 bottom
C2566  -  [C_0402NEW]  296.16 126.8 180 bottom
C2567  -  [C_0402NEW]  297.17 126.8 0 bottom
C2568  -  [C_0402NEW]  288.42 127.69 180 top
C2569  -  [C_0402NEW]  297.07 126.7 180 top
C2570  -  [C_0402NEW]  291.62 141.15 180 top
C2571  -  [C_0402NEW]  297.05 127.69 180 top
C2572  -  [C_0603NEW]  300.2 127.58 180 top
C2573  -  [C_0603NEW]  299.53 141.32 0 top
C2574  -  [C_0603NEW]  302.11 131.25 270 top
C2575  -  [C_0603NEW]  296.58 141.32 0 top
C2576  -  [C_0603NEW]  302.86 131.21 270 bottom
C2577  -  [C_0603NEW]  299.5 141.94 0 bottom
C2578  -  [C_0603NEW]  302.86 134.26 90 bottom
C2579  -  [C_0603NEW]  302.22 139.98 90 top
C2580  -  [C_0603NEW]  287.75 141.18 0 top
C2581  -  [C_0603NEW]  302.86 139.84 90 bottom
C2582  -  [C_0603NEW]  302.24 134.28 90 top
C2583  -  [C_0402NEW]  289.12 132.7 180 top
C2584  -  [C_0402NEW]  290.61 132.69 0 top
C2585  -  [C_0402NEW]  297.33 141.81 0 bottom
C2586  -  [C_0402NEW]  297.08 133.66 180 top
C2587  -  [C_0402NEW]  291.43 135.87 0 top
C2588  -  [C_0402NEW]  298.92 134.98 0 top
C2589  -  [C_0402NEW]  289 135.87 180 top
C2590  -  [C_0402NEW]  290.3 126.85 180 bottom
C2591  -  [C_0402NEW]  290.27 127.69 180 top
C2592  -  [C_0402NEW]  296.34 141.81 180 bottom
C2593  -  [C_0603NEW]  300.77 108.54 0 bottom
C2594  -  [C_0603NEW]  302.86 112.92 270 bottom
C2595  -  [C_0603NEW]  302.86 115.46 90 bottom
C2596  -  [C_0603NEW]  302.86 118.76 90 bottom
C2597  -  [C_0603NEW]  297.75 109.57 0 top
C2598  -  [C_0603NEW]  302.11 112.91 270 top
C2599  -  [C_0603NEW]  302.09 115.41 90 top
C2600  -  [C_0603NEW]  302.1 118.76 90 top
C2601  -  [C_0603NEW]  300.37 109.57 0 top
C2602  -  [C_0603NEW]  287.81 109.68 0 top
C2603  -  [C_0603NEW]  299.12 123.03 0 top
C2604  -  [C_0402NEW]  296.31 108.79 0 bottom
C2605  -  [C_0402NEW]  296.08 123.78 180 bottom
C2606  -  [C_0402NEW]  287.95 123.78 180 bottom
C2607  -  [C_0402NEW]  298.09 108.79 0 bottom
C2608  -  [C_0402NEW]  297.71 123.78 0 bottom
C2609  -  [C_0402NEW]  291.38 109.68 180 top
C2610  -  [C_0402NEW]  299.33 115.42 0 top
C2611  -  [C_0402NEW]  289.86 123.78 180 bottom
C2612  -  [C_0402NEW]  297.28 116.89 180 top
C2613  -  [C_0402NEW]  294.58 113.9 0 top
C2614  -  [C_0402NEW]  292.41 117.91 180 top
C2615  -  [C_0402NEW]  291.3 114.66 0 top
C2616  -  [C_0402NEW]  289.08 114.74 180 top
C2617  -  [C_0402NEW]  289.05 117.91 180 top
C2618  -  [C_0402NEW]  288.21 122.99 180 top
C2619  -  [C_0402NEW]  290.04 122.99 180 top
C2620  -  [C_0402NEW]  297.02 122.91 0 top
C2621  -  [C_0402NEW]  293.28 122.91 0 top
C2622  -  [C_0402NEW]  275.94 89.03 90 bottom
C2623  -  [C_0402NEW]  274.26 94.13 90 top
C2624  -  [C_0402NEW]  268.32 87.13 90 top
C2625  -  [C_0402NEW]  269.74 91.22 270 top
C2626  -  [C_0402NEW]  259.91 89.58 90 bottom
C2627  -  [C_0402NEW]  259.91 88.58 270 bottom
C2628  -  [C_0402NEW]  274.92 88.04 270 bottom
C2629  -  [C_0402NEW]  259.99 97.24 270 bottom
C2630  -  [C_0603NEW]  272.07 83.01 180 bottom
C2631  -  [C_0603NEW]  272.09 83.48 180 top
C2632  -  [C_0603NEW]  264.7 82.88 180 bottom
C2633  -  [C_0603NEW]  273.22 83.51 0 top
C2634  -  [C_0603NEW]  260.38 83.77 0 top
C2635  -  [C_0603NEW]  276.58 84.85 270 bottom
C2636  -  [C_0603NEW]  273.21 82.88 0 bottom
C2637  -  [C_0603NEW]  260.69 85.54 90 top
C2638  -  [C_0603NEW]  274.43 89.16 270 top
C2639  -  [C_0603NEW]  274.29 98 270 top
C2640  -  [C_0603NEW]  274.43 86.22 270 top
C2641  -  [C_0402NEW]  265.81 94.27 270 top
C2642  -  [C_0402NEW]  260.8 97.33 90 top
C2643  -  [C_0402NEW]  268.98 96.75 90 top
C2644  -  [C_0402NEW]  265.81 96.78 270 top
C2645  -  [C_0402NEW]  268.98 94.32 270 top
C2646  -  [C_0402NEW]  259.03 96.32 90 bottom
C2647  -  [C_0402NEW]  260.8 88.69 90 top
C2648  -  [C_0402NEW]  260.8 95.48 90 top
C2649  -  [C_0402NEW]  266.77 88.67 90 top
C2650  -  [C_0402NEW]  259.81 88.68 90 top
C2651  -  [C_0603NEW]  248.42 83.66 0 bottom
C2652  -  [C_0603NEW]  252.25 83.65 180 bottom
C2653  -  [C_0603NEW]  245.9 83.63 180 top
C2654  -  [C_0603NEW]  248.4 83.66 0 top
C2655  -  [C_0603NEW]  253.43 83.66 0 bottom
C2656  -  [C_0603NEW]  253.38 83.66 0 top
C2657  -  [C_0603NEW]  256.9 88.35 270 bottom
C2658  -  [C_0603NEW]  256.01 86.62 270 top
C2659  -  [C_0603NEW]  242.67 97.04 90 top
C2660  -  [C_0603NEW]  242.55 88 270 top
C2661  -  [C_0603NEW]  242.55 85.38 270 top
C2662  -  [C_0402NEW]  257.75 96.81 270 bottom
C2663  -  [C_0402NEW]  256.79 95.93 90 bottom
C2664  -  [C_0402NEW]  257.96 88.04 270 bottom
C2665  -  [C_0402NEW]  256.79 89.68 90 bottom
C2666  -  [C_0402NEW]  249.88 88.47 90 top
C2667  -  [C_0402NEW]  250.9 93.34 90 top
C2668  -  [C_0402NEW]  241.78 88.67 270 bottom
C2669  -  [C_0402NEW]  256.71 85.5 270 bottom
C2670  -  [C_0402NEW]  255.9 92.47 270 top
C2671  -  [C_0402NEW]  255.98 95.7 90 top
C2672  -  [C_0402NEW]  255.98 97.53 90 top
C2673  -  [C_0402NEW]  250.9 96.7 90 top
C2674  -  [C_0402NEW]  255.9 88.75 90 top
C2675  -  [C_0402NEW]  247.72 96.67 90 top
C2676  -  [C_0402NEW]  247.64 94.45 270 top
C2677  -  [C_0402NEW]  242.54 93.86 90 top
C2678  -  [C_0402NEW]  246.88 91.17 270 top
C2679  -  [C_0402NEW]  248.41 86.42 270 top
C2680  -  [C_0402NEW]  300.83 82.81 90 top
C2682  -  [C_0402NEW]  292.45 77.98 90 top
C2683  -  [C_0402NEW]  300.58 56.01 90 top
C2684  -  [C_0603NEW]  221.65 151.21 180 top
C2685  -  [C_0402NEW]  206.73 125.5 270 top
C2686  -  [C_0402NEW]  286.61 171.86 270 top
C2687  -  [C_0402NEW]  76.22 76.91 0 top
C2688  -  [C_0402NEW]  67.15 68.61 270 bottom
C2689  -  [C_0603NEW]  58.19 83.33 90 top
C2690  -  [C_0603NEW]  56.92 83.33 90 top
C2692  -  [C_0402NEW]  240.3 45.93 0 top
C2693  -  [C_0402NEW]  257.65 57.81 270 top
C2694  -  [C_0402NEW]  203.22 197.01 0 top
C2695  -  [C_0402NEW]  211.09 198.71 0 top
C2696  -  [C_0402NEW]  207.44 166.2 180 top
C2701  -  [C_0402NEW]  16.17 148.67 180 top
C2715  -  [C_0402NEW]  73.63 93.25 270 bottom
C2716  -  [C_0402NEW]  87.42 77.17 180 top
C2717  -  [C_0402NEW]  14.96 67.19 90 top
C2718  -  [C_0402NEW]  18.31 63.07 0 top
C2719  -  [C_0402NEW]  19.78 34.57 270 top
C2720  -  [C_0402NEW]  11.91 38.48 90 bottom
C2721  -  [C_0402NEW]  80.89 87.2 180 top
C2722  -  [C_0402NEW]  80.69 84.28 180 top
C2723  -  [C_0402NEW]  307.99 103.33 0 top
C2724  -  [C_0402NEW]  289.05 19.87 0 top
CM3  DLW21HN900HQ2L_4P  [MURAT_DLW21HN900HQ2L_4P]  17.28 130.4 0 top
CM4  DLW21HN900HQ2L_4P  [MURAT_DLW21HN900HQ2L_4P]  17.28 128.5 0 top
CM5  DLW21HN900HQ2L_4P  [MURAT_DLW21HN900HQ2L_4P]  17.28 126.72 0 top
CM6  DLW21HN900HQ2L_4P  [MURAT_DLW21HN900HQ2L_4P]  17.28 132.18 0 top
CM10  DLW21HN900HQ2L_4P  [MURAT_DLW21HN900HQ2L_4P]  16.9 27.47 0 top
CM11  DLW21HN900HQ2L_4P  [MURAT_DLW21HN900HQ2L_4P]  17.28 29.5 0 top
CM12  DLW21HN900HQ2L_4P  [MURAT_DLW21HN900HQ2L_4P]  17.28 39.18 90 top
CM13  DLW21HN900HQ2L_4P  [MURAT_DLW21HN900HQ2L_4P]  20.86 57.32 0 top
CM14  DLW21HN900HQ2L_4P  [MURAT_DLW21HN900HQ2L_4P]  20.86 59.48 0 top
CM15  DLW21HN900HQ2L_4P  [MURAT_DLW21HN900HQ2L_4P]  17.65 57.53 90 bottom
D1  -  [SDM10U45LP-7_DFN1006-2-2]  28.51 56.21 180 bottom
D2  -  [SDM10U45LP-7_DFN1006-2-2]  32.45 53.42 180 top
D3  -  [SDM10U45LP-7_DFN1006-2-2]  28.51 57.48 180 bottom
D4  -  [SDM10U45LP-7_DFN1006-2-2]  31.82 60.02 180 bottom
D5  -  [SDM10U45LP-7_DFN1006-2-2]  41.91 46.82 0 bottom
D6  AZC099-04S.R7G_SOT23-6  [AZC099-04SPR7G_SOT23-6]  36.27 94.5 270 bottom
D7  AZC099-04S.R7G_SOT23-6  [AZC099-04SPR7G_SOT23-6]  36.27 100.5 270 bottom
D8  -  [SDM10U45LP-7_DFN1006-2-2]  287.24 39.93 270 top
D9  -  [SDM10U45LP-7_DFN1006-2-2]  294.69 32.48 180 bottom
D10  -  [SDM10U45LP-7_DFN1006-2-2]  294.69 33.62 180 bottom
D19  -  [SDM10U45LP-7_DFN1006-2-2]  279.37 26.97 270 top
D20  -  [SDM10U45LP-7_DFN1006-2-2]  183.96 196.04 180 top
D22  -  [AIES12U020R2_0402-2]  13.1 162.09 270 bottom
D23  -  [AIES12U020R2_0402-2]  15.72 159.07 90 top
D24  -  [AIES12U020R2_0402-2]  15.72 162.02 270 top
D26  -  [TPD4EUSB30DQAR_SON10]  15.08 132.78 270 top
D27  -  [AIES12U020R2_0402-2]  13.19 134.32 180 top
D28  -  [AIES12U020R2_0402-2]  13.19 135.72 180 top
D29  -  [AIES12U020R2_0402-2]  13.19 136.86 180 top
D30  -  [TPD4EUSB30DQAR_SON10]  15.08 129.22 270 top
D33  -  [AZ5315_0402-3]  18.13 55.58 0 bottom
D37  -  [AIES12U020R2_0402-2]  68.3 19.88 90 bottom
D38  -  [SDM10U45LP-7_DFN1006-2-2]  78.58 19.67 90 top
D39  -  [SDM10U45LP-7_DFN1006-2-2]  79.63 19.64 0 top
D40  -  [AIES12U020R2_0402-2]  275.8 21.67 0 top
D41  -  [AIES12U020R2_0402-2]  274.3 21.67 180 top
D48  -  [AIES12U020R2_0402-2]  68.3 22.82 270 bottom
D49  -  [AZ5315_0402-3]  15.34 37.67 90 top
D51  -  [SDM10U45LP-7_DFN1006-2-2]  289.66 69.71 90 top
D52  -  [SDM10U45LP-7_DFN1006-2-2]  241.78 109.08 90 bottom
D53  -  [TPD4EUSB30DQAR_SON10]  14.57 29.91 270 top
D54  -  [TPD4EUSB30DQAR_SON10]  18.58 59.88 270 top
D55  -  [AIES12U020R2_0402-2]  107.41 3.01 270 top
D56  -  [AIES12U020R2_0402-2]  9.79 72.75 0 top
D57  -  [AIES12U020R2_0402-2]  8.34 72.75 180 top
D58  -  [AIES12U020R2_0402-2]  17.88 77.54 90 top
D59  -  [AIES12U020R2_0402-2]  17.75 79.95 90 top
D60  -  [ESD101_0201-2]  14.15 82.63 90 top
D61  -  [ESD101_0201-2]  14.15 83.55 270 top
D62  -  [ESD101_0201-2]  14.15 83.55 270 bottom
D63  -  [ESD101_0201-2]  14.15 82.63 90 bottom
D64  -  [ESD101_0201-2]  4.98 76.95 90 bottom
D65  -  [ESD101_0201-2]  4.98 77.87 270 bottom
D66  -  [ESD101_0201-2]  14.05 77.81 270 top
D67  -  [ESD101_0201-2]  14.05 76.89 90 top
D69  -  [SDM10U45LP-7_DFN1006-2-2]  289.66 73.84 270 top
D70  -  [SDM10U45LP-7_DFN1006-2-2]  289.66 71.61 90 top
D71  -  [SDM10U45LP-7_DFN1006-2-2]  288.51 71.61 90 top
D2004  -  [AZ5123-01F_0402-2]  12.59 77.17 270 bottom
D2005  -  [AZ5315_0402-3]  14.19 79.3 270 top
D2006  -  [AZ5315_0402-3]  11.02 79.33 0 bottom
D2007  -  [SDM10U45LP-7_DFN1006-2-2]  300.1 84.79 0 top
D2009  -  [SDM10U45LP-7_DFN1006-2-2]  297.81 67.77 0 top
D2010  -  [SDM10U45LP-7_DFN1006-2-2]  297.81 66.63 0 top
D2011  -  [SDM10U45LP-7_DFN1006-2-2]  239.01 116.92 0 top
D2012  -  [SDM10U45LP-7_DFN1006-2-2]  294.26 74.88 0 top
D2013  -  [SDM10U45LP-7_DFN1006-2-2]  288.51 73.84 270 top
D2014  -  [SDM10U45LP-7_DFN1006-2-2]  18 139.56 90 top
D2015  -  [SDM10U45LP-7_DFN1006-2-2]  16.86 139.56 90 top
D2016  -  [SDM10U45LP-7_DFN1006-2-2]  45.56 47.61 90 bottom
D2017  -  [SDM10U45LP-7_DFN1006-2-2]  288.51 69.71 90 top
D2018  -  [TPD4EUSB30DQAR_SON10]  15.79 154.78 270 top
D2019  -  [TPD4EUSB30DQAR_SON10]  15.79 158.18 270 top
D2020  -  [SDM10U45LP-7_DFN1006-2-2]  297.81 65.1 0 top
DL1  -  [D-4_315X3_62-2_3H]  17.75 109.17 180 top
G2  -  [BGA_2152_P070_375X375]  253.74 131.02 90 bottom
H2  -  [HOLE217_98]  265.5 13.69 0 top
H4  -  [HOLE217_98]  209.5 39.46 0 top
H5  -  [HOLE217_98]  111.5 2.69 0 top
H6  -  [HOLE217_98]  261.5 39.5 0 top
H7  -  [HOLE217_98]  20.5 2.69 0 top
H8  -  [HOLE217_98]  27 108.5 0 top
H9  -  [HOLE217_98]  124 40.5 0 top
H10  -  [HOLE217_98]  179.3 201.5 0 top
H12  -  [HOLE217_98]  303.14 7.69 0 top
H13  -  [HOLE197_118]  14.69 171.15 0 top
H14  -  [HOLE394_118]  99.3 114.01 0 top
H15  -  [HOLE335_118]  111 178.5 0 top
H16  -  [HOLE335_118]  308 178.5 0 top
H17  -  [HOLET275B197_166]  280 111.17 0 top
H18  -  [HOLET275B197_166]  246.84 155.06 0 top
H19  -  [HOLET275B197_166]  228.19 111.08 0 top
H20  -  [HOLET275B197_166]  198.65 121.02 0 top
H21  -  [HOLET275B197_166]  176.11 164.67 0 top
H22  -  [HOLET275B197_166]  138.77 131.13 0 top
H23  -  [HOLE217_98]  8.69 171.15 0 top
H24  -  [HOLE217_98]  6 68.5 0 top
H26  -  [HOLE217_98]  101.47 96.48 0 top
H27  -  [HOLE217_98]  57.5 2.69 0 top
H28  -  [HOLE217_98]  311 117.69 0 top
H29  -  [HOLE276_98]  209.5 88.6 0 top
H30  -  [HOLEOB297X197_197X118]  296.67 7.69 0 top
J1  JUMPER  [J_0202]  35.47 51.51 0 top
J2  JUMPER  [J_0202]  290.58 32.34 0 bottom
J3  JUMPER  [J_0202]  295.75 37.74 270 top
JBAT1  -  [DOCK-12502HB012M200ZL-12P-L]  100.55 14.18 270 bottom
JCAM1  -  [50376-00801-V01-8P-L]  162.21 198.85 0 bottom
JDBUG1  -  [KRYO_046809605020846_5P-T]  39.51 4.25 90 bottom
JDCIN1  -  [50458-00901-001-9P]  24.42 24.65 90 bottom
JDIMM1  -  [DDR-5_2-80886-100-260P]  165.94 83.47 180 bottom
JDIMM2  -  [DDR-80888-100-260P]  164.28 83.47 0 top
JDIMM3  -  [DDR-5_2-80888-100-260P]  166.17 70.27 0 bottom
JDIMM4  -  [DDR-80886-100-260P]  164.48 70.27 180 top
JDP1  -  [DP-DRA45-00-00-20P-R]  4 158.3 270 top
JEC1  -  [KRYO_046299626120846_26P-T]  63.72 51.26 180 bottom
JEDP1  -  [50398-04071-001-40P]  196.82 201.22 0 bottom
JFAN1  -  [WS33041-S0351-HF-4P]  296.51 73.28 270 bottom
JFAN2  -  [WS33041-S0351-HF-4P]  92.68 96.35 90 bottom
JHDD1  ACES_50208-01001-001  [ACES_50208-01001-001_10P]  294.25 88.98 270 bottom
JHDMI1  -  [HDMI-2HE3Y36-000111F-19P]  7.1 131.75 270 top
JIO1  -  [CONN76-0_4-33_35X4_9X1_3MM]  300.43 37.92 270 bottom
JKB1  -  [006800650012846-50P-L]  79.34 12.02 180 bottom
JRJ1  -  [RJ45-JM3611-RS800003-7H-8P]  4.78 103.05 270 top
JRTC1  ACES_50271-0020N-001  [ACES_50271-0020N-001_2P]  80.87 20.74 90 bottom
JSPBL1  -  [50208-00601-001-6P]  309.47 102.95 270 bottom
JSPKR1  -  [50281-00401-001-4P]  296.84 61.67 270 bottom
JSSD1  -  [NGFF-NFSM0-S6710-TP50-75P-KM]  100.7 50.42 90 bottom
JSSD2  -  [NGFF-NFSM0-S6710-TP50-75P-KM]  100.68 74.79 90 bottom
JSWF1  ACES_50271-0020N-001  [ACES_50271-0020N-001_2P]  294.5 52.1 180 bottom
JTP1  -  [FC1AF061-1201H-6P]  274.35 20.91 180 bottom
JTPBL1  -  [FC1AF061-1201H-6P]  287.35 20.91 180 bottom
JTYPC1  -  [USB-UT11111-13401-7H-24P]  7.45 79.32 270 top
JUSB1  -  [USB-UAA111C-441R1-7H-9P]  10.59 55.3 270 top
JUSB2  -  [UB3-UEA1111-R36AM1-7H-9P]  4.45 29.2 270 top
JWLAN1  -  [MINIPCI-80152-001-75P]  271.5 73.56 180 bottom
L1  -  [MURAT_BLM15BD221SN1D_2P]  30.58 52.27 270 top
L2  -  [MURAT_BLM15BD221SN1D_2P]  30.58 49.74 90 top
L3  -  [MURAT_BLM15BD221SN1D_2P]  44.67 52.66 180 bottom
L4  -  [L4X4-1_2H]  54.2 65.84 270 top
L5  -  [L1_6X0_8]  54.71 58.37 180 bottom
L6  -  [L1_6X0_8]  51.66 58.37 180 bottom
L7  -  [MURAT_BLM15PX121SN1D_2P]  289.4 41.09 270 top
L8  -  [MURAT_BLM15PX121SN1D_2P]  291.15 40.92 270 bottom
L11  -  [MURAT_BLM15PX121SN1D_2P]  266.29 28.79 90 bottom
L12  -  [MURAT_BLM15PX121SN1D_2P]  279.5 29.03 270 top
L18  -  [L1_6X0_8-T0_8MM]  223.11 125.81 180 top
L20  -  [L1_6X0_8-T0_8MM]  223.11 124.79 180 top
L21  -  [MURAT_BLM15BD221SN1D_2P]  62.45 9.34 270 top
L38  -  [MURAT_BLM15PX121SN1D_2P]  241.19 47.46 90 top
L39  -  [MURAT_BLM15PX121SN1D_2P]  257.65 55.95 270 top
L2001  -  [MURAT_LQM18PN1R0M_2P]  60.04 83.52 180 top
L2002  -  [L1_6X0_8-T0_8MM]  85.31 18.49 90 top
L2003  -  [MURAT_BLM15BD221SN1D_2P]  86.58 18.87 270 top
L2004  -  [L1_6X0_8-T0_8MM]  77.31 15.95 0 top
L2005  -  [L1_6X0_8-T0_8MM]  77.31 17.73 0 top
L2006  -  [L1_6X0_8-T0_8MM]  77.31 16.84 0 top
L2007  -  [L1_6X0_8-T0_8MM]  290.55 18.75 0 top
L2008  -  [MURAT_BLM15BD221SN1D_2P]  290.92 17.61 180 top
L2009  -  [L1_6X0_8-T0_8MM]  283.43 23.32 180 top
L2010  -  [L1_6X0_8-T0_8MM]  283.43 24.34 180 top
L2012  -  [L1_6X0_8-T0_8MM]  307.44 101.81 270 top
L2013  -  [MURAT_BLM15BD221SN1D_2P]  308.58 101.43 90 top
L2014  -  [L1_6X0_8-T0_8MM]  303.88 99.65 180 top
L2015  -  [L1_6X0_8-T0_8MM]  303.88 100.66 180 top
LD1  -  [LED-FSL-2408035WA-3P]  4.41 173.18 90 top
NOREF  -  [unnamed]  5.18 15.95 0 top
NOREF#2  -  [unnamed]  17.77 167.52 0 top
NOREF#3  -  [#2]  1.75 254 0 top
NOREF#4  -  [#2]  189.29 279.73 0 top
NOREF#5  -  [unnamed]  308.58 204.3 0 top
NOREF#6  -  [unnamed]  265.32 8.08 0 top
NOREF#7  -  [unnamed]  308.58 204.3 180 bottom
NOREF#8  -  [unnamed]  5.18 15.95 180 bottom
NOREF#9  -  [unnamed]  265.32 8.08 180 bottom
NOREF#10  -  [unnamed]  17.77 167.52 180 bottom
NUT1  -  [HOLE240_126]  22.45 50.42 0 top
NUT2  -  [HOLE240_126]  22.43 74.79 0 top
NUT3  -  [HOLE240_126]  271.5 45.29 0 top
PC9  -  [C_0402NEW]  306.79 196.95 90 bottom
PC10  -  [C_0603NEW]  298.92 200.26 270 bottom
PC11  -  [C_0603NEW]  301.5 204.35 270 bottom
PC12  -  [C_0402NEW]  209.39 124.46 90 bottom
PC13  -  [C_0402NEW]  208.81 120.35 0 bottom
PC14  VAL  [1005_BGA]  275.56 76.53 270 top
PC15  -  [C_0402NEW]  277.29 74.37 180 top
PC23  0.1U_0603_16V7K  [C_0603]  268.19 202.58 90 bottom
PC101  -  [C_0402NEW]  82.98 25.1 180 bottom
PC102  -  [C_0402NEW]  82.06 24.21 0 bottom
PC103  -  [C_0402NEW]  94.91 22.05 180 bottom
PC104  -  [C_0402NEW]  29.48 21.8 0 top
PC105  -  [C_0402NEW]  29.48 22.94 0 top
PC106  -  [C_0402NEW]  28.93 37.34 90 top
PC107  -  [C_0402NEW]  28.04 37.34 90 top
PC108  -  [C_0402NEW]  31.47 56.39 90 top
PC128  -  [C_0805NEW]  32.39 24.59 0 top
PC190  -  [C_0402NEW]  299.74 89.36 0 top
PC191  -  [C_0402NEW]  298.67 173.89 270 top
PC192  -  [C_0402NEW]  216.25 108.21 90 bottom
PC193  -  [C_EEEFK1E680P]  117.95 169.37 180 bottom
PC194  -  [C_EEEFK1E680P]  110.21 99.9 0 bottom
PC195  -  [C_EEEFK1E680P]  146.22 189.06 90 bottom
PC196  -  [C_0402]  302.94 94.31 0 bottom
PC201  -  [C_0402NEW]  35.22 38.94 180 top
PC202  -  [C_0402NEW]  37.48 37.04 0 top
PC203  -  [C_0402NEW]  102.64 20.65 0 top
PC204  0.1U_0603_16V7K  [C_0603]  273.53 50.69 90 top
PC205  -  [C_0603NEW]  79.66 13.67 180 top
PC206  -  [C_0603NEW]  80.68 13.67 0 top
PC207  -  [C_0402NEW]  85.82 13.21 90 top
PC208  -  [C_0805NEW]  102.97 26.03 90 top
PC209  -  [C_0805NEW]  106.52 26.03 90 top
PC210  -  [C_0805NEW]  101.19 26.03 90 top
PC211  -  [C_0805NEW]  110.08 26.03 90 top
PC212  -  [C_0402NEW]  91.33 12.65 0 top
PC213  -  [C_0402NEW]  87.17 6.18 180 top
PC214  -  [C_0603NEW]  92.74 7.83 0 top
PC215  -  [C_0603NEW]  91.98 9.22 0 top
PC216  -  [C_0402NEW]  89.18 5.23 270 top
PC217  -  [C_0402NEW]  85.83 5.23 270 top
PC218  -  [C_0402NEW]  78.63 8.72 0 top
PC219  -  [C_0402NEW]  78.63 7.83 0 top
PC220  -  [C_0603NEW]  91.22 6.56 0 top
PC221  -  [C_0402NEW]  81.17 4.02 0 top
PC222  -  [C_0402NEW]  80.23 4.07 90 top
PC223  -  [C_0402NEW]  80.94 11.89 180 top
PC224  -  [C_0603NEW]  79.74 14.94 0 top
PC225  -  [C_0805NEW]  98.18 13.8 0 top
PC226  -  [C_0805NEW]  93.4 16.34 180 top
PC227  -  [C_0805NEW]  93.4 14.43 180 top
PC228  -  [C_0805NEW]  108.3 26.03 90 top
PC229  -  [C_0805NEW]  104.74 26.03 90 top
PC230  0.1U_0603_16V7K  [C_0603]  274.8 52.09 270 top
PC231  -  [C_0402NEW]  86.76 12.78 0 top
PC301  -  [C_0402NEW]  39.34 20.35 270 top
PC303  -  [C_0603NEW]  43.91 8.91 90 top
PC304  -  [C_0805NEW]  54.62 26.37 0 top
PC305  -  [C_0805NEW]  40.86 20.74 270 top
PC306  -  [C_0805NEW]  44.56 22.18 0 top
PC307  -  [C_0603NEW]  44.74 23.83 0 top
PC308  -  [C_0805NEW]  37.01 24.62 180 top
PC309  -  [C_0603NEW]  39.94 13.41 0 top
PC310  -  [C_0603NEW]  47.91 13.8 0 top
PC312  -  [C_B2]  28.67 5.52 90 top
PC313  -  [C_0603NEW]  56.42 11.51 0 top
PC314  -  [C_0603NEW]  38.45 6.62 270 top
PC315  -  [C_0603NEW]  45.5 17.99 0 top
PC316  -  [C_0603NEW]  44.48 17.99 180 top
PC317  -  [C_0402NEW]  47.9 12.65 0 top
PC318  -  [C_B2]  25.37 5.52 90 top
PC319  -  [C_B2]  62.22 19.64 180 top
PC320  -  [C_B2]  62.22 16.34 180 top
PC321  -  [C_B2]  62.22 13.03 180 top
PC322  -  [C_B2]  31.97 5.52 90 top
PC401  0.1U_0603_16V7K  [C_0603]  111.89 86.44 0 top
PC402  -  [C_0402NEW]  109.24 82.55 0 top
PC403  0.1U_0603_16V7K  [C_0603]  114.65 93.49 270 bottom
PC404  -  [C_0805NEW]  108.59 79.45 0 bottom
PC405  -  [C_0805NEW]  108.59 79.45 0 top
PC406  -  [C_0805NEW]  114.02 93.46 90 top
PC407  -  [C_0805NEW]  112.24 93.46 90 top
PC408  -  [C_B2]  117.42 74.73 0 bottom
PC409  -  [C_B2]  117.42 77.93 0 bottom
PC410  -  [C_0402]  109.82 92.46 90 top
PC411  -  [C_0402]  109.44 86.77 270 top
PC412  -  [C_0402NEW]  118.64 89.23 0 bottom
PC413  -  [C_0402]  106.65 91.72 270 top
PC414  -  [C_0402]  101.32 87.13 90 top
PC415  -  [C_0402]  100.43 87.13 90 top
PC416  -  [C_0402NEW]  275.46 58.78 180 bottom
PC417  -  [C_0805NEW]  108.52 83.9 0 top
PC418  -  [C_0805NEW]  108.59 81.23 0 top
PC419  -  [C_0402NEW]  215.11 116.87 270 top
PC420  -  [C_0805NEW]  215.2 118.95 180 top
PC421  -  [C_0402NEW]  209.75 112.04 180 top
PC422  -  [C_0805NEW]  212.44 103.42 270 top
PC423  -  [C_0805NEW]  210.83 94.69 0 top
PC424  -  [C_0603NEW]  211.7 113.84 270 bottom
PC425  -  [C_0805NEW]  209.27 106.54 90 top
PC426  -  [C_0805NEW]  210.83 96.47 0 top
PC428  -  [C_0402NEW]  213.43 112.37 90 bottom
PC433  -  [C_0402NEW]  107.41 91.44 90 bottom
PC434  -  [C_0603NEW]  211.55 118.38 90 top
PC435  -  [C_0402NEW]  208.83 114.2 0 bottom
PC436  -  [C_0805NEW]  215.2 118.95 180 bottom
PC437  -  [C_0603NEW]  209.77 116.6 90 top
PC438  -  [C_0805NEW]  206.98 106.54 90 top
PC439  -  [C_0402]  106.19 89.87 0 top
PC501  -  [C_0402NEW]  261.28 45.57 0 top
PC502  -  [C_0805NEW]  260.74 43.77 0 top
PC503  -  [C_0805NEW]  258.9 46.63 90 top
PC504  -  [C_0603NEW]  266.1 51.01 180 top
PC505  -  [C_0805NEW]  264.95 60.61 0 top
PC506  -  [C_0805NEW]  261.12 61.5 180 top
PC507  -  [C_0805NEW]  264.93 58.88 0 top
PC508  -  [C_0805NEW]  264.93 62.34 0 top
PC510  -  [C_0805NEW]  261.12 59.8 180 top
PC511  -  [C_0402NEW]  265.04 50.73 0 bottom
PC512  -  [C_0603NEW]  265.53 47.26 270 top
PC513  -  [C_0603NEW]  265.08 43.77 0 top
PC514  -  [C_0402NEW]  265.65 55.12 90 top
PC515  -  [C_0402NEW]  266.62 48.09 180 bottom
PC601  -  [C_0402NEW]  77.29 56.77 0 top
